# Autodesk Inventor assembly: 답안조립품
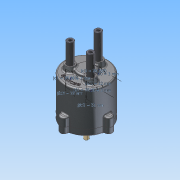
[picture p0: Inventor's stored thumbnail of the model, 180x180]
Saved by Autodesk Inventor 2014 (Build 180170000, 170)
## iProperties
Created: 2015-09
Part Number: 답안조립품
Document SubType Name: Assembly
Designer: study
Mass: 2160.14 g
Surface Area: 1801.25 cm^2
Volume: 438.509 cm^3
Density: 4.92611 g/cm^3
Author: study
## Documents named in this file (14)
- C:\Users\study\Desktop\350916V1011\답안조립품.iam
- C:\Users\study\Desktop\350916V1011\몸체.ipt
- C:\Users\study\Desktop\350916V1011\M5x0.8x20.ipt
- C:\Users\study\Desktop\350916V1011\오일실.ipt
- C:\Users\study\Desktop\350916V1011\커버.ipt
- C:\Users\study\Desktop\350916V1011\메인 축.ipt
- C:\Users\study\Desktop\350916V1011\멈춤링 10 x 1.ipt
- C:\Users\study\Desktop\350916V1011\멈춤링 22 x 1.2.ipt
- C:\Users\study\Desktop\350916V1011\판캠.ipt
- C:\Users\study\Desktop\350916V1011\베어링 NA 4900.ipt
- C:\Users\study\Desktop\350916V1011\슬라이드 축.ipt
- C:\Users\study\Desktop\350916V1011\11-가변 스프링.ipt
- C:\Users\study\Desktop\350916V1011\12-가변 스프링.ipt
- C:\Users\study\Desktop\350916V1011\13-가변 스프링.ipt
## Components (7 placed, 4 different names)
1. 11-가변 스프링:1
2. 12-가변 스프링:1
3. 13-가변 스프링:1
4. M5x0.8x20:1
5. M5x0.8x20:2
6. M5x0.8x20:3
7. M5x0.8x20:4
